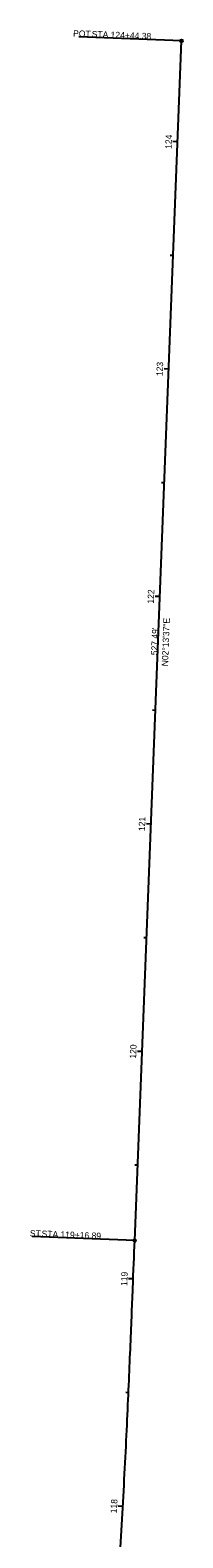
# Model space of a CAD drawing. Extents: x 1832834 to 1833221, y 712492 to 713942.
# Drawn here: x 1833154 to 1833221, y 713279 to 713942 of the extents above; entities that cross this region are included whole.
import ezdxf

# ---------------------------------------------------------------- set-up
doc = ezdxf.new("R2010")
doc.units = 0
for name, color, linetype in [('DT_X_Contour_Major', 7, 'Continuous'), ('DT_X_Contour_Minor', 7, 'Continuous'), ('DT_X_Island', 7, 'Continuous'), ('DT_X_Spot_Elev', 7, 'Continuous'), ('DT_X_Void', 7, 'Continuous')]:
    doc.layers.add(name, color=color, linetype=linetype)

msp = doc.modelspace()

# ---------------------------------------------------------------- linework, layer by layer
at = {"layer": 'DT_X_Contour_Minor'}
msp.add_line((1833200.1, 713410.07), (1833220.6, 713937.16), dxfattribs=at)
msp.add_open_spline([(1833159.11, 713012.83), (1833160.63, 713019.32), (1833163.56, 713032.33), (1833168.93, 713058.45), (1833174.81, 713091.27), (1833180.64, 713130.85), (1833185.41, 713170.56), (1833189.26, 713210.38), (1833192.35, 713250.26), (1833194.83, 713290.19), (1833196.84, 713330.14), (1833198.26, 713363.44), (1833199.33, 713390.08), (1833199.84, 713403.41), (1833200.1, 713410.07)], degree=3, dxfattribs=at)
at = {"layer": 'DT_X_Spot_Elev'}
for p, q in [((1833220.6, 713937.16), (1833175.63, 713938.91)), ((1833200.1, 713410.07), (1833155.14, 713411.82))]:
    msp.add_line(p, q, dxfattribs=at)
for centre in [(1833220.6, 713937.16), (1833200.1, 713410.07)]:
    msp.add_circle(centre, 0.6, dxfattribs=at)
at = {"layer": 'DT_X_Void'}
for p, q in [((1833218.87, 713892.81), (1833216.88, 713892.89)), ((1833216.93, 713842.85), (1833215.73, 713842.9)), ((1833214.99, 713792.89), (1833212.99, 713792.97)), ((1833213.05, 713742.93), (1833211.85, 713742.97)), ((1833211.1, 713692.96), (1833209.1, 713693.04)), ((1833209.16, 713643), (1833207.96, 713643.05)), ((1833207.22, 713593.04), (1833205.22, 713593.12)), ((1833205.27, 713543.08), (1833204.08, 713543.12)), ((1833203.33, 713493.12), (1833201.33, 713493.19)), ((1833201.39, 713443.15), (1833200.19, 713443.2)), ((1833199.44, 713393.19), (1833197.45, 713393.27)), ((1833197.38, 713343.23), (1833196.19, 713343.29)), ((1833194.92, 713293.29), (1833192.93, 713293.41))]:
    msp.add_line(p, q, dxfattribs=at)

# ---------------------------------------------------------------- texts
at = {"layer": 'DT_X_Contour_Major'}
msp.add_text('N02°13\'37"E', height=2.8, rotation=87.77316, dxfattribs=at).set_placement((1833214.72, 713662.32))
at = {"layer": 'DT_X_Island'}
msp.add_text("527.49'", height=2.8, rotation=87.77316, dxfattribs=at).set_placement((1833210.06, 713667.18))
at = {"layer": 'DT_X_Spot_Elev'}
for s, p in [('POT', (1833173.05, 713939.04)), (' STA. ', (1833180.18, 713938.77)), ('124+44.38', (1833189.49, 713938.4)), ('ST', (1833154.09, 713411.89)), (' STA. ', (1833158.2, 713411.74)), ('119+16.89', (1833167.51, 713411.37))]:
    msp.add_text(s, height=2.8, rotation=357.77316, dxfattribs=at).set_placement(p)
at = {"layer": 'DT_X_Void'}
for s, rotation, p in [('124', 87.77316, (1833216.25, 713889.63)), ('123', 87.77316, (1833212.37, 713789.79)), ('122', 87.77316, (1833208.48, 713689.85)), ('121', 87.77316, (1833204.59, 713589.92)), ('120', 87.77316, (1833200.71, 713489.95)), ('119', 87.75355, (1833196.82, 713390.07)), ('118', 86.83381, (1833192.25, 713290.19))]:
    msp.add_text(s, height=2.8, rotation=rotation, dxfattribs=at).set_placement(p)

doc.saveas('drawing.dxf')
